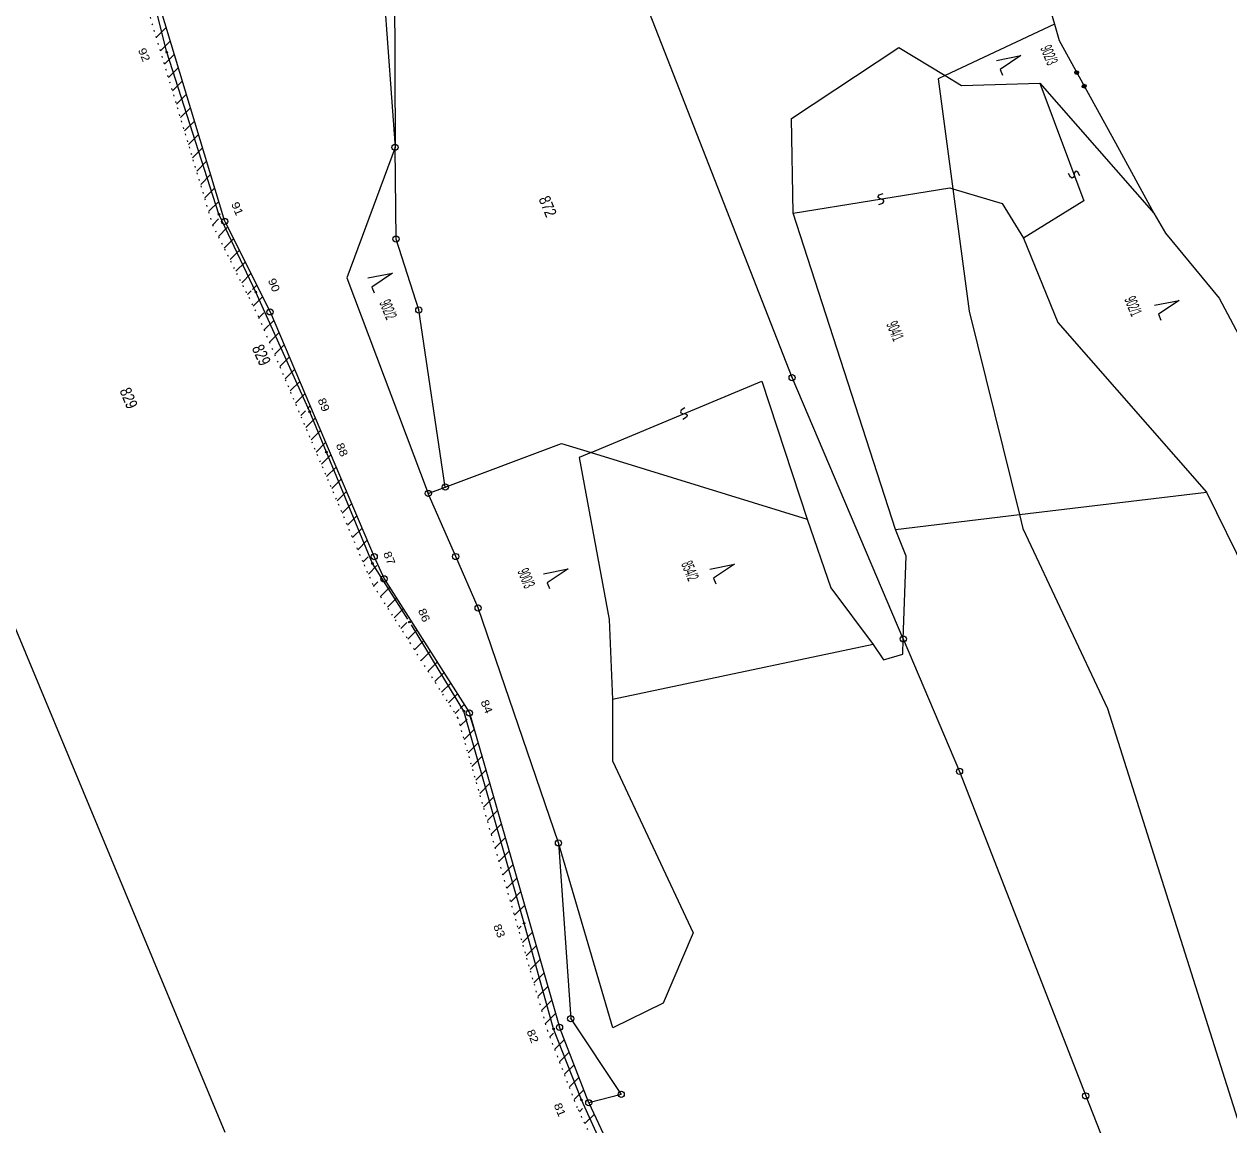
# Model space of a CAD drawing. Extents: x -687415 to -686486, y -959539 to -958099.
# Drawn here: x -687103.2 to -686809.7, y -958988.8 to -958720.6 of the extents above; entities that cross this region are included whole.
import ezdxf
from ezdxf.enums import TextEntityAlignment as Align

# ---------------------------------------------------------------- set-up
doc = ezdxf.new("R2010")
doc.units = 0
doc.header["$LTSCALE"] = 1.1
doc.linetypes.add('DOTTED', pattern=[1.5, 0.3, -1.2])
for name, color, linetype, lineweight in [('1', 7, 'Continuous', 13), ('2', 7, 'Continuous', 25), ('3', 7, 'Continuous', 13)]:
    doc.layers.add(name, color=color, linetype=linetype, lineweight=lineweight)

msp = doc.modelspace()

# ---------------------------------------------------------------- linework, layer by layer
at = {"layer": '1', "linetype": 'DOTTED', "lineweight": 25}
for p, q in [((-687057.18, -958769.8), (-687075.59, -958708.62)), ((-687046.06, -958791.98), (-687057.18, -958769.8)), ((-687020.69, -958851.59), (-687046.06, -958791.98)), ((-687018.22, -958857.22), (-687020.69, -958851.59)), ((-686997.52, -958889.7), (-687018.22, -958857.22)), ((-686975.64, -958966.01), (-686997.52, -958889.7)), ((-686968.42, -958984.64), (-686975.64, -958966.01)), ((-686907.24, -959115.56), (-686968.42, -958984.64))]:
    msp.add_line(p, q, dxfattribs=at)
at = {"layer": '1'}
for p, q in [((-686916.12, -958806.75), (-686954.39, -958708.82)), ((-687015.62, -958712.38), (-687012.86, -958750.65)), ((-686852.2, -958720.65), (-686878.83, -958733.14)), ((-686847.02, -958732.581), (-686846.494, -958732.292)), ((-686878.83, -958733.14), (-686880.55, -958733.95)), ((-686880.55, -958733.95), (-686876.95, -958760.76)), ((-686878.83, -958733.14), (-686874.82, -958735.56)), ((-686874.82, -958735.56), (-686855.72, -958734.98)), ((-686855.72, -958734.98), (-686827.97, -958766.65)), ((-686845.214, -958735.867), (-686844.688, -958735.578)), ((-687012.62, -958773), (-687012.86, -958750.65)), ((-686876.95, -958760.76), (-686864.91, -958764.31)), ((-686876.95, -958760.76), (-686872.95, -958790.57)), ((-687148.11, -958765.28), (-687054.31, -958990.59)), ((-687007.07, -958790.27), (-687012.62, -958773)), ((-687000.62, -958833.42), (-687007.07, -958790.27)), ((-686872.95, -958790.57), (-686860.7, -958840.13)), ((-686889.03, -958870.44), (-686916.12, -958806.75)), ((-687004.77, -958834.98), (-687000.62, -958833.42)), ((-686860.7, -958840.13), (-686815.11, -958834.64)), ((-686896.38, -958871.82), (-686959.91, -958885.2)), ((-686994.663, -958889.249), (-686993.533, -958892.727)), ((-686973.04, -958920.13), (-686970.07, -958962.96)), ((-686965.66, -958983.46), (-686972.79, -958965.06))]:
    msp.add_line(p, q, dxfattribs=at)
for points in [[(-687033.26, -958388.56), (-687005.99, -958371.61), (-686997.96, -958352.78), (-686994.69, -958366.72), (-686990.71, -958408.32), (-686984.42, -958474.05), (-686978.41, -958545.96), (-686975.7, -958570.97), (-686972.53, -958606.08), (-686970.99, -958659.13), (-686979.46, -958677.41), (-686989.6, -958689.79), (-686997.77, -958698.21), (-687012.99, -958711.74), (-687012.86, -958750.65)], [(-687054.36, -958768.69), (-687072.61, -958708.09), (-687075.54, -958660.66), (-687082.37, -958591.19)], [(-686876.14, -958648.4), (-686865.05, -958675.56), (-686856.78, -958704.76), (-686852.2, -958720.65), (-686851.06, -958724.61), (-686837.34, -958749.57), (-686827.97, -958766.65), (-686825.14, -958771.59), (-686812.07, -958787.37), (-686794.44, -958820.54), (-686780.59, -958846.06), (-686777.25, -958855.45)], [(-686890.94, -958843.77), (-686915.88, -958766.67), (-686916.28, -958743.58), (-686890.12, -958726.35), (-686878.83, -958733.14)], [(-686866.346, -958729.479), (-686860.344, -958728.291), (-686865.428, -958731.696), (-686864.854, -958733.082)], [(-686846.744, -958732.772), (-686846.481, -958732.627), (-686846.422, -958732.423), (-686846.948, -958732.712), (-686847.092, -958732.449), (-686846.567, -958732.16), (-686846.77, -958732.101), (-686847.033, -958732.246)], [(-686855.72, -958734.98), (-686845.01, -958763.67), (-686859.76, -958772.74)], [(-686844.938, -958736.058), (-686844.675, -958735.913), (-686844.616, -958735.71), (-686845.141, -958735.999), (-686845.286, -958735.736), (-686844.76, -958735.447), (-686844.964, -958735.388), (-686845.227, -958735.532)], [(-687012.86, -958750.65), (-687024.62, -958782.45), (-687004.77, -958834.98)], [(-686846.002, -958757.579), (-686846.51, -958756.648), (-686846.896, -958756.471), (-686847.177, -958756.576), (-686847.353, -958756.962), (-686847.424, -958757.629), (-686847.601, -958758.015), (-686847.882, -958758.12), (-686848.268, -958757.944), (-686848.775, -958757.013)], [(-686915.88, -958766.67), (-686877.72, -958760.53), (-686876.95, -958760.76)], [(-686895.018, -958764.528), (-686894.005, -958764.213), (-686893.756, -958763.87), (-686893.804, -958763.573), (-686894.148, -958763.325), (-686894.788, -958763.124), (-686895.132, -958762.875), (-686895.179, -958762.579), (-686894.931, -958762.235), (-686893.918, -958761.92)], [(-686864.91, -958764.31), (-686859.76, -958772.74), (-686851.37, -958793.34), (-686815.11, -958834.64)], [(-687054.36, -958768.69), (-687043.33, -958790.73), (-687017.94, -958850.39), (-687015.55, -958855.78), (-686994.76, -958888.45), (-686972.79, -958965.06)], [(-687019.469, -958782.461), (-687013.466, -958781.274), (-687018.55, -958784.678), (-687017.976, -958786.064)], [(-686827.774, -958789.108), (-686821.771, -958787.921), (-686826.855, -958791.326), (-686826.281, -958792.711)], [(-686965.1, -958825.02), (-686923.52, -958807.58), (-686912.47, -958841.27)], [(-686942.272, -958814.144), (-686943.182, -958814.688), (-686943.343, -958815.081), (-686943.227, -958815.357), (-686942.834, -958815.518), (-686942.165, -958815.563), (-686941.772, -958815.723), (-686941.656, -958816), (-686941.817, -958816.393), (-686942.727, -958816.937)], [(-687000.62, -958833.42), (-686972.33, -958822.78), (-686965.1, -958825.02), (-686912.47, -958841.27)], [(-686965.1, -958825.02), (-686967.97, -958826.22), (-686960.69, -958865.65), (-686959.91, -958885.2), (-686959.84, -958900.1), (-686940.19, -958942.08), (-686947.5, -958959.21), (-686959.83, -958965.2), (-686973.04, -958920.13), (-686992.63, -958862.88), (-686998.09, -958850.34), (-687004.77, -958834.98)], [(-686815.11, -958834.64), (-686805.51, -958854.31), (-686782.73, -958855.23), (-686777.25, -958855.45), (-686769.17, -958878.16), (-686758.67, -958907.68), (-686744.98, -958948.05), (-686719.22, -959023.5), (-686699.65, -959080.73), (-686683.05, -959115.22), (-686652.59, -959178.05), (-686618.25, -959249.24), (-686597.25, -959289.88), (-686633.86, -959286.61), (-686711.27, -959277.22), (-686727.83, -959274.04), (-686744.23, -959269.58), (-686747.57, -959266.6), (-686749.25, -959266.14)], [(-686912.47, -958841.27), (-686906.66, -958857.94), (-686896.38, -958871.82)], [(-686890.94, -958843.77), (-686860.7, -958840.13), (-686859.87, -958843.5), (-686839.25, -958887.41), (-686807.64, -958987.21), (-686805.21, -958987.76), (-686798.91, -958993.27), (-686793.12, -958986.35), (-686782.13, -959004.96), (-686751.25, -959075.9), (-686722.86, -959159.17), (-686749.25, -959266.14)], [(-686889.03, -958870.44), (-686888.29, -958850.28), (-686890.94, -958843.77)], [(-686936.189, -958853.418), (-686930.186, -958852.23), (-686935.27, -958855.635), (-686934.696, -958857.021)], [(-686976.712, -958854.546), (-686970.709, -958853.359), (-686975.793, -958856.764), (-686975.219, -958858.149)], [(-686896.38, -958871.82), (-686893.83, -958875.54), (-686889.17, -958874.1), (-686889.03, -958870.44)], [(-686889.03, -958870.44), (-686875.32, -958902.69), (-686844.58, -958981.76)], [(-686970.07, -958962.96), (-686957.75, -958981.41), (-686965.66, -958983.46), (-686904.35, -959114.65)], [(-686844.58, -958981.76), (-686831.48, -959015.02), (-686807.1, -959066.85), (-686799.98, -959082.42), (-686779.98, -959145.99)]]:
    msp.add_lwpolyline(points, dxfattribs=at)
for points in [[(-687068.685, -958727.378), (-687068.408, -958727.264), (-687068.294, -958727.541), (-687068.571, -958727.655)], [(-686846.409, -958732.759), (-686846.672, -958732.903), (-686847.079, -958732.785), (-686847.224, -958732.522), (-686847.105, -958732.114), (-686846.843, -958731.97), (-686846.435, -958732.088), (-686846.291, -958732.351)], [(-686844.603, -958736.045), (-686844.866, -958736.189), (-686845.273, -958736.071), (-686845.417, -958735.808), (-686845.299, -958735.401), (-686845.036, -958735.256), (-686844.629, -958735.374), (-686844.484, -958735.637)], [(-687055.955, -958766.858), (-687055.678, -958766.744), (-687055.564, -958767.021), (-687055.841, -958767.135)], [(-687046.985, -958785.808), (-687046.708, -958785.694), (-687046.594, -958785.971), (-687046.871, -958786.085)], [(-687033.835, -958814.968), (-687033.558, -958814.854), (-687033.444, -958815.131), (-687033.721, -958815.245)], [(-687029.795, -958824.798), (-687029.518, -958824.684), (-687029.404, -958824.961), (-687029.681, -958825.075)], [(-687018.565, -958851.938), (-687018.288, -958851.824), (-687018.174, -958852.101), (-687018.451, -958852.215)], [(-687009.552, -958866.231), (-687009.275, -958866.116), (-687009.16, -958866.393), (-687009.437, -958866.508)], [(-686996.275, -958887.908), (-686995.998, -958887.794), (-686995.884, -958888.071), (-686996.161, -958888.185)], [(-686981.615, -958939.608), (-686981.338, -958939.494), (-686981.224, -958939.771), (-686981.501, -958939.885)], [(-686974.435, -958965.368), (-686974.158, -958965.254), (-686974.044, -958965.531), (-686974.321, -958965.645)], [(-686967.665, -958982.668), (-686967.388, -958982.554), (-686967.274, -958982.831), (-686967.551, -958982.945)]]:
    msp.add_lwpolyline(points, close=True, dxfattribs=at)
for centre, radius in [((-687012.86, -958750.65), 0.75), ((-687012.86, -958750.65), 0.015), ((-687054.36, -958768.69), 0.75), ((-687054.36, -958768.69), 0.015), ((-687012.62, -958773), 0.75), ((-687012.62, -958773), 0.015), ((-687043.33, -958790.73), 0.75), ((-687043.33, -958790.73), 0.015), ((-687007.07, -958790.27), 0.75), ((-687007.07, -958790.27), 0.015), ((-686916.12, -958806.75), 0.75), ((-686916.12, -958806.75), 0.015), ((-687004.77, -958834.98), 0.75), ((-687004.77, -958834.98), 0.015), ((-687000.62, -958833.42), 0.75), ((-687000.62, -958833.42), 0.015), ((-687017.94, -958850.39), 0.75), ((-686998.09, -958850.34), 0.75), ((-687017.94, -958850.39), 0.015), ((-686998.09, -958850.34), 0.015), ((-687015.55, -958855.78), 0.75), ((-687015.55, -958855.78), 0.015), ((-686992.63, -958862.88), 0.75), ((-686992.63, -958862.88), 0.015), ((-686889.03, -958870.44), 0.75), ((-686889.03, -958870.44), 0.015), ((-686994.76, -958888.45), 0.75), ((-686994.76, -958888.45), 0.015), ((-686875.32, -958902.69), 0.75), ((-686875.32, -958902.69), 0.015), ((-686973.04, -958920.13), 0.75), ((-686973.04, -958920.13), 0.015), ((-686972.79, -958965.06), 0.75), ((-686970.07, -958962.96), 0.75), ((-686970.07, -958962.96), 0.015), ((-686972.79, -958965.06), 0.015), ((-686957.75, -958981.41), 0.75), ((-686957.75, -958981.41), 0.015), ((-686844.58, -958981.76), 0.75), ((-686844.58, -958981.76), 0.015), ((-686965.66, -958983.46), 0.75), ((-686965.66, -958983.46), 0.015)]:
    msp.add_circle(centre, radius, dxfattribs=at)
at = {"layer": '2'}
for points in [[(-687009.759, -958865.649), (-687018.37, -958852.02), (-687029.6, -958824.88), (-687033.64, -958815.05), (-687046.79, -958785.89), (-687055.76, -958766.94), (-687068.49, -958727.46), (-687073.69, -958706.75), (-687075.68, -958682.24), (-687076.43, -958662.93), (-687081.17, -958616.15), (-687085.06, -958567.54), (-687089.27, -958519.84), (-687094.154, -958472.067)], [(-686892.32, -959234.647), (-686921.66, -959227.39), (-686919.79, -959218.39), (-686903.68, -959159.32), (-686901.8, -959149.35), (-686901.46, -959137.17), (-686903.97, -959120.31), (-686907.01, -959111.23), (-686930.33, -959062.07), (-686954.03, -959012.27), (-686967.47, -958982.75), (-686974.24, -958965.45), (-686981.42, -958939.69), (-686996.08, -958887.99), (-687008.875, -958867.027)]]:
    msp.add_lwpolyline(points, dxfattribs=at)
at = {"layer": '3'}
for p, q in [((-687071.014, -958723.825), (-687068.598, -958721.41)), ((-687070.032, -958727.087), (-687067.616, -958724.67)), ((-687069.051, -958730.348), (-687066.634, -958727.931)), ((-687068.07, -958733.609), (-687065.652, -958731.192)), ((-687067.088, -958736.87), (-687064.67, -958734.452)), ((-687066.107, -958740.132), (-687063.688, -958737.713)), ((-687065.126, -958743.393), (-687062.706, -958740.974)), ((-687064.144, -958746.654), (-687061.724, -958744.234)), ((-687063.163, -958749.916), (-687060.742, -958747.495)), ((-687062.182, -958753.177), (-687059.76, -958750.756)), ((-687061.2, -958756.438), (-687058.778, -958754.016)), ((-687060.219, -958759.699), (-687057.796, -958757.277)), ((-687059.237, -958762.961), (-687056.814, -958760.538)), ((-687058.256, -958766.222), (-687055.833, -958763.798)), ((-687057.275, -958769.483), (-687055.86, -958768.068)), ((-687055.9, -958772.351), (-687053.737, -958770.188)), ((-687054.483, -958775.177), (-687052.237, -958772.931)), ((-687053.067, -958778.003), (-687050.822, -958775.758)), ((-687051.65, -958780.829), (-687049.407, -958778.586)), ((-687050.233, -958783.655), (-687047.992, -958781.413)), ((-687048.816, -958786.481), (-687047.899, -958785.563)), ((-687047.577, -958785.242), (-687046.577, -958784.241)), ((-687047.4, -958789.307), (-687045.162, -958787.069)), ((-687045.991, -958792.141), (-687044.83, -958790.979)), ((-687044.724, -958795.117), (-687042.436, -958792.828)), ((-687043.458, -958798.093), (-687041.17, -958795.805)), ((-687042.191, -958801.069), (-687039.903, -958798.781)), ((-687040.925, -958804.045), (-687038.637, -958801.757)), ((-687039.658, -958807.021), (-687037.37, -958804.733)), ((-687038.391, -958809.997), (-687036.103, -958807.709)), ((-687037.125, -958812.973), (-687034.837, -958810.685)), ((-687035.858, -958815.949), (-687034.715, -958814.805)), ((-687034.229, -958814.319), (-687033.57, -958813.661)), ((-687034.592, -958818.925), (-687032.304, -958816.637)), ((-687033.325, -958821.901), (-687031.037, -958819.613)), ((-687032.058, -958824.877), (-687029.771, -958822.589)), ((-687030.792, -958827.853), (-687028.504, -958825.565)), ((-687029.525, -958830.829), (-687027.238, -958828.541)), ((-687028.259, -958833.805), (-687025.971, -958831.518)), ((-687026.992, -958836.781), (-687024.704, -958834.494)), ((-687025.725, -958839.757), (-687023.438, -958837.47)), ((-687024.459, -958842.733), (-687022.171, -958840.446)), ((-687023.192, -958845.709), (-687020.905, -958843.422)), ((-687021.926, -958848.685), (-687019.638, -958846.398)), ((-687020.658, -958851.661), (-687019.44, -958850.442)), ((-687019.365, -958854.61), (-687017.31, -958852.555)), ((-687018.03, -958857.517), (-687017.05, -958856.537)), ((-687016.378, -958860.109), (-687014.188, -958857.919)), ((-687014.727, -958862.7), (-687012.538, -958860.511)), ((-687013.075, -958865.291), (-687010.888, -958863.104)), ((-687011.424, -958867.882), (-687009.99, -958866.448)), ((-687009.773, -958870.473), (-687007.589, -958868.289)), ((-687008.121, -958873.065), (-687005.939, -958870.882)), ((-687006.47, -958875.656), (-687004.289, -958873.475)), ((-687004.818, -958878.247), (-687002.639, -958876.068)), ((-687003.167, -958880.838), (-687000.989, -958878.66)), ((-687001.515, -958883.43), (-686999.339, -958881.253)), ((-686999.864, -958886.021), (-686997.689, -958883.846)), ((-686998.213, -958888.612), (-686997.211, -958887.61)), ((-686996.995, -958887.395), (-686996.039, -958886.439)), ((-686996.971, -958891.613), (-686995.306, -958889.948)), ((-686996.025, -958894.91), (-686993.602, -958892.486)), ((-686995.08, -958898.207), (-686992.656, -958895.784)), ((-686994.135, -958901.505), (-686991.711, -958899.081)), ((-686993.189, -958904.802), (-686990.765, -958902.378)), ((-686992.244, -958908.099), (-686989.82, -958905.675)), ((-686991.298, -958911.396), (-686988.874, -958908.972)), ((-686990.353, -958914.694), (-686987.929, -958912.269)), ((-686989.408, -958917.991), (-686986.983, -958915.566)), ((-686988.462, -958921.288), (-686986.038, -958918.863)), ((-686987.517, -958924.585), (-686985.092, -958922.16)), ((-686986.571, -958927.883), (-686984.146, -958925.458)), ((-686985.626, -958931.18), (-686983.201, -958928.755)), ((-686984.681, -958934.477), (-686982.255, -958932.052)), ((-686983.735, -958937.774), (-686981.31, -958935.349)), ((-686982.79, -958941.071), (-686982.105, -958940.387)), ((-686981.844, -958944.369), (-686979.419, -958941.943)), ((-686980.899, -958947.666), (-686978.473, -958945.24)), ((-686979.954, -958950.963), (-686977.528, -958948.537)), ((-686979.008, -958954.26), (-686976.582, -958951.834)), ((-686978.063, -958957.558), (-686975.637, -958955.131)), ((-686977.117, -958960.855), (-686974.691, -958958.429)), ((-686976.172, -958964.152), (-686973.746, -958961.726)), ((-686975.122, -958967.345), (-686974.29, -958966.512)), ((-686973.937, -958970.402), (-686971.618, -958968.083)), ((-686972.752, -958973.46), (-686970.433, -958971.141)), ((-686971.567, -958976.518), (-686969.248, -958974.199)), ((-686970.382, -958979.575), (-686968.063, -958977.256)), ((-686969.197, -958982.633), (-686966.878, -958980.314)), ((-686967.955, -958985.634), (-686967.16, -958984.838)), ((-686966.604, -958988.525), (-686964.347, -958986.268))]:
    msp.add_line(p, q, dxfattribs=at)

# ---------------------------------------------------------------- texts
at = {"layer": '1'}
for s, height, rotation, width, p in [('92', 1.95, 292.5, 1.15, (-687075.534, -958726.913)), ('902/3', 2.85, 292.5, 0.5, (-686855.68, -958726.477)), ('91', 1.95, 292.5, 1.15, (-687052.825, -958764.42)), ('90', 1.95, 292.5, 1.15, (-687043.886, -958783.023)), ('904/1', 2.85, 292.5, 0.5, (-686893.22, -958793.72)), ('829', 3, 294.3, 0.75, (-687047.821, -958799.564)), ('89', 1.95, 292.5, 1.15, (-687031.773, -958812.188)), ('88', 1.95, 292.5, 1.15, (-687027.317, -958823.14)), ('87', 1.95, 292.5, 1.15, (-687015.801, -958849.555)), ('86', 1.95, 292.5, 1.15, (-687007.318, -958863.46)), ('84', 1.95, 292.5, 1.15, (-686992.062, -958885.744)), ('83', 1.95, 292.5, 1.15, (-686988.991, -958940.378)), ('82', 1.95, 292.5, 1.15, (-686980.838, -958966.051)), ('81', 1.95, 292.5, 1.15, (-686974.23, -958983.975))]:
    msp.add_text(s, height=height, rotation=rotation, dxfattribs=dict(at, width=width)).set_placement(p)
for s, width, p in [('872', 0.8, (-686976.969, -958765.577)), ('902/2', 0.5, (-687015.832, -958790.695)), ('902/1', 0.5, (-686834.311, -958789.862)), ('829', 0.8, (-687079.064, -958812.282)), ('854/2', 0.5, (-686942.279, -958854.365)), ('900/3', 0.5, (-686982.176, -958856.171))]:
    msp.add_text(s, height=2.85, rotation=292.5, dxfattribs=dict(at, width=width)).set_placement(p, align=Align.CENTER)

doc.saveas('drawing.dxf')
